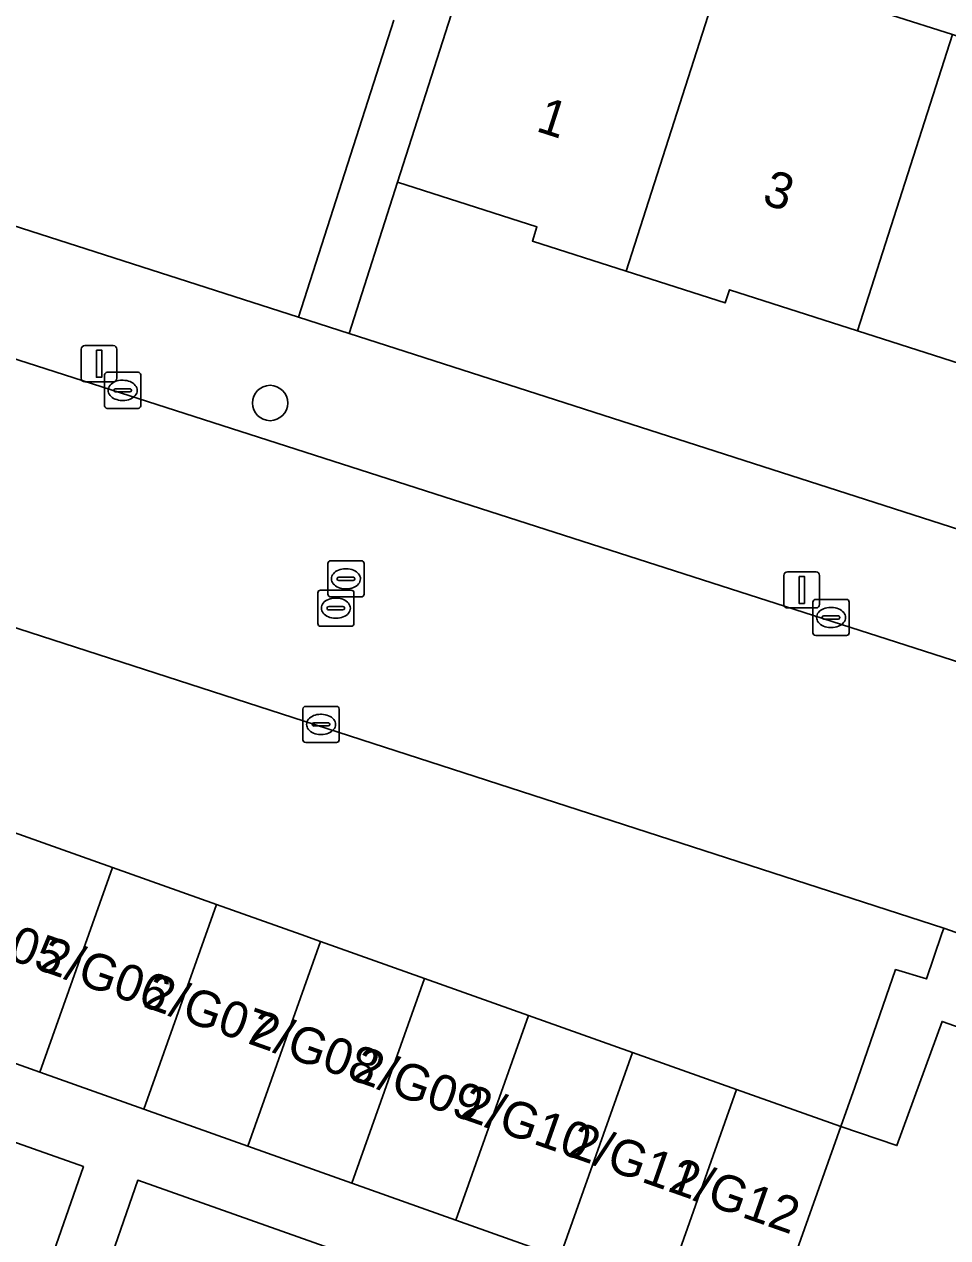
# Model space of a CAD drawing. Extents: x 163266 to 164362, y 381528 to 382286.
# Drawn here: x 163775.55 to 163801.11, y 381991.61 to 382025.18 of the extents above; entities that cross this region are included whole.
import ezdxf

# ---------------------------------------------------------------- set-up
doc = ezdxf.new("R2010")
doc.units = 0
for name, color, linetype in [('IMGEO_Boom', 7, 'Continuous'), ('IMGEO_Erf', 7, 'Continuous'), ('IMGEO_Groenvoorziening', 7, 'Continuous'), ('IMGEO_Kolk', 7, 'Continuous'), ('IMGEO_Lichtmast', 7, 'Continuous'), ('IMGEO_Pand', 7, 'Continuous'), ('IMGEO_Pand_nummerreeks', 7, 'Continuous'), ('IMGEO_Parkeervlak_open', 7, 'Continuous'), ('IMGEO_Rijbaan_lokaal_open', 7, 'Continuous'), ('IMGEO_Rioolput', 7, 'Continuous'), ('IMGEO_Voetpad_open', 7, 'Continuous')]:
    doc.layers.add(name, color=color, linetype=linetype)

msp = doc.modelspace()

# ---------------------------------------------------------------- linework, layer by layer
at = {"layer": 'IMGEO_Boom'}
msp.add_circle((163782.359, 382014.702), 0.489, dxfattribs=at)
at = {"layer": 'IMGEO_Erf'}
for points in [[(163776.384, 382030.962), (163774.693, 382024.796), (163773.431, 382020.194), (163783.143, 382017.074), (163785.784, 382025.296)], [(163797.866, 382025.977), (163801.242, 382024.894)], [(163802.156, 382015.564), (163798.615, 382016.7), (163795.075, 382017.835), (163794.957, 382017.469), (163792.216, 382018.348), (163789.618, 382019.181), (163789.743, 382019.572), (163785.887, 382020.808), (163784.545, 382016.624), (163836.291, 382000)], [(163776.163, 381990.625), (163777.19, 381993.583), (163766.425, 381997.378), (163764.459, 381991.803), (163762.425, 381986.032)], [(163790.056, 381989.188), (163778.694, 381993.201), (163777.673, 381990.259)]]:
    msp.add_lwpolyline(points, dxfattribs=at)
at = {"layer": 'IMGEO_Groenvoorziening'}
msp.add_lwpolyline([(163802.138, 381997.175), (163800.958, 381997.595), (163799.707, 381994.161), (163798.155, 381994.686), (163796.14, 381989.033), (163801.584, 381987.098), (163804.03, 381994.157)], dxfattribs=at)
at = {"layer": 'IMGEO_Kolk'}
for p, q in [((163777.777, 382014.626), (163777.777, 382015.478)), ((163777.852, 382015.552), (163778.704, 382015.552)), ((163778.778, 382015.478), (163778.778, 382014.626)), ((163778.036, 382015.046), (163778.036, 382015.058)), ((163778.079, 382015.095), (163778.477, 382015.095)), ((163778.265, 382015.332), (163778.29, 382015.332)), ((163778.52, 382015.058), (163778.52, 382015.046)), ((163778.474, 382015.009), (163778.076, 382015.009)), ((163778.288, 382014.772), (163778.263, 382014.772)), ((163778.704, 382014.552), (163777.852, 382014.552)), ((163797.384, 382008.344), (163797.384, 382009.196)), ((163797.459, 382009.27), (163798.311, 382009.27)), ((163797.872, 382009.05), (163797.897, 382009.05)), ((163798.385, 382009.196), (163798.385, 382008.344)), ((163797.643, 382008.764), (163797.643, 382008.776)), ((163798.081, 382008.727), (163797.683, 382008.727)), ((163797.686, 382008.813), (163798.084, 382008.813)), ((163798.127, 382008.776), (163798.127, 382008.764)), ((163797.895, 382008.49), (163797.87, 382008.49)), ((163798.311, 382008.27), (163797.459, 382008.27)), ((163783.343, 382006.311), (163784.195, 382006.311)), ((163783.268, 382005.385), (163783.268, 382006.237)), ((163783.756, 382006.091), (163783.781, 382006.091)), ((163784.269, 382006.237), (163784.269, 382005.385)), ((163783.527, 382005.805), (163783.527, 382005.817)), ((163783.965, 382005.768), (163783.567, 382005.768)), ((163783.57, 382005.854), (163783.968, 382005.854)), ((163784.011, 382005.817), (163784.011, 382005.805)), ((163784.195, 382005.311), (163783.343, 382005.311)), ((163783.779, 382005.531), (163783.754, 382005.531))]:
    msp.add_line(p, q, dxfattribs=at)
for points in [[(163777.777, 382014.626), (163777.777, 382015.478)], [(163777.852, 382015.552), (163778.704, 382015.552)], [(163778.778, 382015.478), (163778.778, 382014.626)], [(163778.704, 382014.552), (163777.852, 382014.552)], [(163797.384, 382008.344), (163797.384, 382009.196)], [(163797.459, 382009.27), (163798.311, 382009.27)], [(163798.385, 382009.196), (163798.385, 382008.344)], [(163798.311, 382008.27), (163797.459, 382008.27)], [(163783.343, 382006.311), (163784.195, 382006.311)], [(163783.268, 382005.385), (163783.268, 382006.237)], [(163784.269, 382006.237), (163784.269, 382005.385)], [(163784.195, 382005.311), (163783.343, 382005.311)]]:
    msp.add_lwpolyline(points, dxfattribs=at)
for centre, radius, start, end in [((163777.854, 382015.476), 0.0765, 91.552, 178.448), ((163777.854, 382015.476), 0.0765, 91.552, 178.448), ((163778.702, 382015.476), 0.0765, 1.552, 88.448), ((163778.702, 382015.476), 0.0765, 1.552, 88.448), ((163778.076, 382015.055), 0.0403, 85.8775, 175.7526), ((163778.073, 382015.045), 0.0366, 178.938, 274.7102), ((163778.477, 382015.052), 0.043, 264.8664, 352.4533), ((163778.481, 382015.057), 0.0386, 1.7309, 96.639), ((163777.854, 382014.628), 0.0765, 181.552, 268.448), ((163777.854, 382014.628), 0.0765, 181.552, 268.448), ((163778.702, 382014.628), 0.0765, 271.552, 358.448), ((163778.702, 382014.628), 0.0765, 271.552, 358.448), ((163797.461, 382009.194), 0.0765, 91.552, 178.448), ((163797.461, 382009.194), 0.0765, 91.552, 178.448), ((163798.309, 382009.194), 0.0765, 1.552, 88.448), ((163798.309, 382009.194), 0.0765, 1.552, 88.448), ((163797.683, 382008.773), 0.0403, 85.8775, 175.7526), ((163797.68, 382008.763), 0.0366, 178.938, 274.7102), ((163798.084, 382008.77), 0.043, 264.8664, 352.4533), ((163798.088, 382008.775), 0.0386, 1.7309, 96.639), ((163797.461, 382008.346), 0.0765, 181.552, 268.448), ((163797.461, 382008.346), 0.0765, 181.552, 268.448), ((163798.309, 382008.346), 0.0765, 271.552, 358.448), ((163798.309, 382008.346), 0.0765, 271.552, 358.448), ((163783.345, 382006.235), 0.0765, 91.552, 178.448), ((163783.345, 382006.235), 0.0765, 91.552, 178.448), ((163784.193, 382006.235), 0.0765, 1.552, 88.448), ((163784.193, 382006.235), 0.0765, 1.552, 88.448), ((163783.567, 382005.814), 0.0403, 85.8775, 175.7526), ((163783.564, 382005.804), 0.0366, 178.938, 274.7102), ((163783.968, 382005.811), 0.043, 264.8664, 352.4533), ((163783.972, 382005.816), 0.0386, 1.7309, 96.639), ((163783.345, 382005.387), 0.0765, 181.552, 268.448), ((163783.345, 382005.387), 0.0765, 181.552, 268.448), ((163784.193, 382005.387), 0.0765, 271.552, 358.448), ((163784.193, 382005.387), 0.0765, 271.552, 358.448)]:
    msp.add_arc(centre, radius, start, end, dxfattribs=at)
for centre, major_axis, ratio, start_param, end_param in [((163778.264, 382015.052), (-0.387, 0.002), 0.722429, 4.712389, 7.853982), ((163778.289, 382015.052), (-0.39, 0.002), 0.717154, 1.570796, 4.712389), ((163797.871, 382008.77), (-0.387, 0.002), 0.722429, 4.712389, 7.853982), ((163797.896, 382008.77), (-0.39, 0.002), 0.717154, 1.570796, 4.712389), ((163783.755, 382005.811), (-0.387, 0.002), 0.722429, 4.712389, 7.853982), ((163783.78, 382005.811), (-0.39, 0.002), 0.717154, 1.570796, 4.712389)]:
    msp.add_ellipse(centre, major_axis=major_axis, ratio=ratio, start_param=start_param, end_param=end_param, dxfattribs=at)
at = {"layer": 'IMGEO_Lichtmast'}
for p, q in [((163777.129, 382015.389), (163777.129, 382016.189)), ((163777.129, 382016.189), (163777.129, 382015.389)), ((163777.229, 382016.289), (163778.019, 382016.289)), ((163778.019, 382016.289), (163777.229, 382016.289)), ((163778.119, 382016.189), (163778.119, 382015.389)), ((163778.119, 382015.389), (163778.119, 382016.189)), ((163778.019, 382015.289), (163777.229, 382015.289)), ((163777.229, 382015.289), (163778.019, 382015.289)), ((163796.678, 382010.032), (163797.468, 382010.032)), ((163797.468, 382010.032), (163796.678, 382010.032)), ((163796.578, 382009.132), (163796.578, 382009.932)), ((163796.578, 382009.932), (163796.578, 382009.132)), ((163797.568, 382009.932), (163797.568, 382009.132)), ((163797.568, 382009.132), (163797.568, 382009.932)), ((163797.468, 382009.032), (163796.678, 382009.032)), ((163796.678, 382009.032), (163797.468, 382009.032))]:
    msp.add_line(p, q, dxfattribs=at)
for points in [[(163777.549, 382016.164), (163777.699, 382016.164), (163777.699, 382015.414), (163777.549, 382015.414), (163777.549, 382016.164)], [(163796.998, 382009.907), (163797.148, 382009.907), (163797.148, 382009.157), (163796.998, 382009.157), (163796.998, 382009.907)]]:
    msp.add_lwpolyline(points, dxfattribs=at)
for centre, start, end in [((163777.229, 382016.189), 90, 180), ((163777.229, 382016.189), 90, 180), ((163778.019, 382016.189), 0, 90), ((163778.019, 382016.189), 360, 90), ((163777.229, 382015.389), 180, 270), ((163777.229, 382015.389), 180, 270), ((163778.019, 382015.389), 270, 0), ((163778.019, 382015.389), 270, 0), ((163796.678, 382009.932), 90, 180), ((163796.678, 382009.932), 90, 180), ((163797.468, 382009.932), 0, 90), ((163797.468, 382009.932), 360, 90), ((163796.678, 382009.132), 180, 270), ((163796.678, 382009.132), 180, 270), ((163797.468, 382009.132), 270, 0), ((163797.468, 382009.132), 270, 0)]:
    msp.add_arc(centre, 0.1, start, end, dxfattribs=at)
at = {"layer": 'IMGEO_Pand'}
for points in [[(163792.216, 382018.348), (163795.26, 382027.844), (163792.852, 382028.616), (163792.431, 382027.367), (163788.663, 382028.576), (163787.679, 382025.506), (163787.373, 382025.44), (163785.887, 382020.808), (163789.743, 382019.572), (163789.618, 382019.181)], [(163801.242, 382024.894), (163797.866, 382025.977), (163798.166, 382026.912), (163795.26, 382027.844), (163792.216, 382018.348), (163794.957, 382017.469), (163795.075, 382017.835), (163798.615, 382016.7)], [(163801.242, 382024.894), (163798.615, 382016.7), (163802.156, 382015.564), (163802.025, 382015.154), (163804.764, 382014.276), (163807.816, 382023.794), (163805.164, 382024.644), (163804.871, 382023.73)], [(163778, 382001.855), (163775.121, 382002.879), (163773.109, 381997.219), (163775.988, 381996.196)], [(163778, 382001.855), (163775.988, 381996.196), (163778.867, 381995.172), (163780.878, 382000.831)], [(163783.757, 381999.808), (163783.216, 382000), (163780.878, 382000.831), (163778.867, 381995.172), (163781.746, 381994.149)], [(163784.625, 381993.126), (163786.636, 381998.784), (163783.757, 381999.808), (163781.746, 381994.149)], [(163784.625, 381993.126), (163787.503, 381992.103), (163789.514, 381997.76), (163786.636, 381998.784)], [(163790.382, 381991.079), (163792.393, 381996.736), (163789.514, 381997.76), (163787.503, 381992.103)], [(163790.382, 381991.079), (163793.261, 381990.056), (163795.271, 381995.712), (163792.393, 381996.736)], [(163795.271, 381995.712), (163793.261, 381990.056), (163796.14, 381989.033), (163798.155, 381994.686)]]:
    msp.add_lwpolyline(points, close=True, dxfattribs=at)
at = {"layer": 'IMGEO_Parkeervlak_open'}
msp.add_lwpolyline([(163799.673, 381999.03), (163800.523, 381998.774), (163800.945, 382000), (163801.005, 382000.175), (163765.277, 382011.726), (163764.019, 382008.065), (163763.613, 382006.973), (163766.485, 382005.951), (163769.364, 382004.927), (163772.243, 382003.903), (163775.121, 382002.879), (163778, 382001.855), (163780.878, 382000.831), (163783.216, 382000), (163783.757, 381999.808), (163786.636, 381998.784), (163789.514, 381997.76), (163792.393, 381996.736), (163795.271, 381995.712), (163798.155, 381994.686), (163798.543, 381995.778)], close=True, dxfattribs=at)
at = {"layer": 'IMGEO_Rijbaan_lokaal_open'}
msp.add_lwpolyline([(163849.853, 381991.631), (163831.384, 381997.714), (163809.167, 382005.041), (163762.591, 382019.997), (163757.318, 382021.706), (163755.403, 382022.326), (163754.211, 382022.697), (163752.053, 382015.936), (163753.214, 382015.593), (163756.256, 382014.586), (163765.277, 382011.726), (163801.005, 382000.175), (163801.506, 382000), (163801.743, 381999.917), (163803.998, 381999.189)], dxfattribs=at)
at = {"layer": 'IMGEO_Rioolput'}
for p, q in [((163784.032, 382010.339), (163784.884, 382010.339)), ((163783.957, 382009.413), (163783.957, 382010.265)), ((163784.445, 382010.119), (163784.47, 382010.119)), ((163784.958, 382010.265), (163784.958, 382009.413)), ((163784.216, 382009.833), (163784.216, 382009.845)), ((163784.654, 382009.796), (163784.256, 382009.796)), ((163784.259, 382009.882), (163784.657, 382009.882)), ((163784.7, 382009.845), (163784.7, 382009.833)), ((163783.678, 382008.6), (163783.678, 382009.452)), ((163783.753, 382009.526), (163784.605, 382009.526)), ((163784.884, 382009.339), (163784.032, 382009.339)), ((163784.468, 382009.559), (163784.443, 382009.559)), ((163784.679, 382009.452), (163784.679, 382008.6)), ((163783.937, 382009.02), (163783.937, 382009.032)), ((163784.375, 382008.983), (163783.977, 382008.983)), ((163783.98, 382009.069), (163784.378, 382009.069)), ((163784.166, 382009.306), (163784.191, 382009.306)), ((163784.421, 382009.032), (163784.421, 382009.02)), ((163784.189, 382008.746), (163784.164, 382008.746)), ((163784.605, 382008.526), (163783.753, 382008.526))]:
    msp.add_line(p, q, dxfattribs=at)
for points in [[(163784.032, 382010.339), (163784.884, 382010.339)], [(163783.957, 382009.413), (163783.957, 382010.265)], [(163784.958, 382010.265), (163784.958, 382009.413)], [(163783.678, 382008.6), (163783.678, 382009.452)], [(163783.753, 382009.526), (163784.605, 382009.526)], [(163784.884, 382009.339), (163784.032, 382009.339)], [(163784.679, 382009.452), (163784.679, 382008.6)], [(163784.605, 382008.526), (163783.753, 382008.526)]]:
    msp.add_lwpolyline(points, dxfattribs=at)
for centre, radius, start, end in [((163784.034, 382010.263), 0.0765, 91.552, 178.448), ((163784.034, 382010.263), 0.0765, 91.552, 178.448), ((163784.882, 382010.263), 0.0765, 1.552, 88.448), ((163784.882, 382010.263), 0.0765, 1.552, 88.448), ((163784.256, 382009.842), 0.0403, 85.8775, 175.7526), ((163784.253, 382009.832), 0.0366, 178.938, 274.7102), ((163784.657, 382009.839), 0.043, 264.8664, 352.4533), ((163784.661, 382009.844), 0.0386, 1.7309, 96.639), ((163783.755, 382009.45), 0.0765, 91.552, 178.448), ((163783.755, 382009.45), 0.0765, 91.552, 178.448), ((163784.034, 382009.415), 0.0765, 181.552, 268.448), ((163784.034, 382009.415), 0.0765, 181.552, 268.448), ((163784.603, 382009.45), 0.0765, 1.552, 88.448), ((163784.603, 382009.45), 0.0765, 1.552, 88.448), ((163784.882, 382009.415), 0.0765, 271.552, 358.448), ((163784.882, 382009.415), 0.0765, 271.552, 358.448), ((163783.977, 382009.029), 0.0403, 85.8775, 175.7526), ((163783.974, 382009.019), 0.0366, 178.938, 274.7102), ((163784.378, 382009.026), 0.043, 264.8664, 352.4533), ((163784.382, 382009.031), 0.0386, 1.7309, 96.639), ((163783.755, 382008.602), 0.0765, 181.552, 268.448), ((163783.755, 382008.602), 0.0765, 181.552, 268.448), ((163784.603, 382008.602), 0.0765, 271.552, 358.448), ((163784.603, 382008.602), 0.0765, 271.552, 358.448)]:
    msp.add_arc(centre, radius, start, end, dxfattribs=at)
for centre, major_axis, ratio, start_param, end_param in [((163784.444, 382009.839), (-0.387, 0.002), 0.722429, 4.712389, 7.853982), ((163784.469, 382009.839), (-0.39, 0.002), 0.717154, 1.570796, 4.712389), ((163784.165, 382009.026), (-0.387, 0.002), 0.722429, 4.712389, 7.853982), ((163784.19, 382009.026), (-0.39, 0.002), 0.717154, 1.570796, 4.712389)]:
    msp.add_ellipse(centre, major_axis=major_axis, ratio=ratio, start_param=start_param, end_param=end_param, dxfattribs=at)
at = {"layer": 'IMGEO_Voetpad_open'}
for points in [[(163785.784, 382025.296), (163783.143, 382017.074), (163784.545, 382016.624), (163785.887, 382020.808), (163787.373, 382025.44)], [(163836.291, 382000), (163784.545, 382016.624), (163783.143, 382017.074), (163773.431, 382020.194), (163770.69, 382021.032), (163765.086, 382022.744), (163758.349, 382025.147), (163757.318, 382021.706), (163762.591, 382019.997), (163809.167, 382005.041), (163831.384, 381997.714), (163849.853, 381991.631), (163896.886, 381976.383)], [(163790.382, 381991.079), (163787.503, 381992.103), (163784.625, 381993.126), (163781.746, 381994.149), (163778.867, 381995.172), (163775.988, 381996.196), (163773.109, 381997.219), (163770.23, 381998.242), (163767.352, 381999.265), (163765.285, 382000), (163764.473, 382000.289), (163761.594, 382001.312), (163763.613, 382006.973), (163762.021, 382007.524), (163759.464, 382000.245), (163760.16, 382000), (163763.957, 381998.664), (163763.827, 381998.294), (163766.425, 381997.378), (163777.19, 381993.583), (163776.163, 381990.625)], [(163803.998, 381999.189), (163801.743, 381999.917), (163801.506, 382000), (163801.005, 382000.175), (163800.945, 382000), (163800.523, 381998.774), (163799.673, 381999.03), (163798.543, 381995.778), (163798.155, 381994.686), (163799.707, 381994.161), (163800.958, 381997.595), (163802.138, 381997.175)], [(163777.673, 381990.259), (163778.694, 381993.201), (163790.056, 381989.188)]]:
    msp.add_lwpolyline(points, dxfattribs=at)

# ---------------------------------------------------------------- texts
at = {"layer": 'IMGEO_Pand_nummerreeks'}
for s, rotation, p in [('1', 342.1892, (163789.686, 382022.234)), ('3', 342.1892, (163795.941, 382020.224)), ('2/G05', 340.641, (163773.032, 382000.047)), ('2/G06', 340.641, (163775.923, 381999.031)), ('2/G07', 340.641, (163778.814, 381998.016)), ('2/G08', 340.641, (163781.707, 381996.999)), ('2/G09', 340.641, (163784.592, 381995.985)), ('2/G10', 340.641, (163787.575, 381994.937)), ('2/G11', 340.641, (163790.566, 381993.886)), ('2/G12', 340.641, (163793.347, 381992.909))]:
    msp.add_text(s, height=1, rotation=rotation, dxfattribs=at).set_placement(p)

doc.saveas('drawing.dxf')
